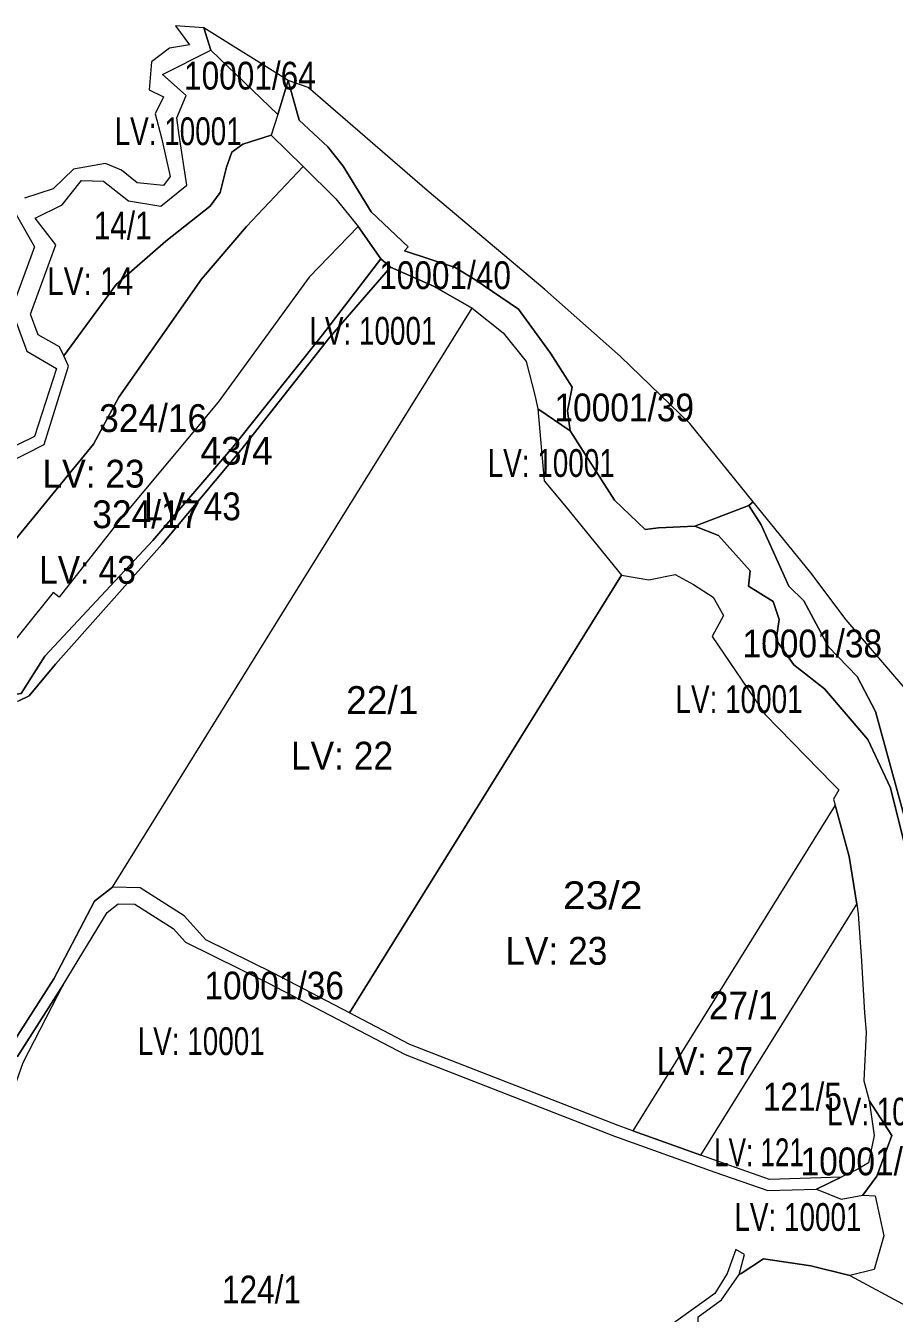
# Model space of a CAD drawing. Extents: x -713758 to -711119, y -1123067 to -1120789.
# Drawn here: x -711860.1 to -711547.6, y -1121251.9 to -1120788.6 of the extents above; entities that cross this region are included whole.
import ezdxf
from ezdxf.enums import TextEntityAlignment as Align

# ---------------------------------------------------------------- set-up
doc = ezdxf.new("R2010")
doc.units = 0
doc.header["$LTSCALE"] = 4
doc.layers.add('10', color=7, linetype='Continuous', lineweight=13)
doc.layers.add('11', color=7, linetype='Continuous')
doc.layers.add('13', color=7, linetype='Continuous')

msp = doc.modelspace()

# ---------------------------------------------------------------- linework, layer by layer
at = {"layer": '10'}
for points in [[(-711873, -1120949.11), (-711853.48, -1120939.28), (-711844.78, -1120911.14), (-711846.49, -1120907.42), (-711847.98, -1120904.16), (-711855.72, -1120899.85), (-711858.44, -1120892.41), (-711849.31, -1120867.47), (-711856.7, -1120857.83), (-711847.04, -1120852.99), (-711840.1, -1120844.3), (-711832.13, -1120844.47), (-711823.14, -1120851.63), (-711811.49, -1120853.48), (-711802.15, -1120845.94), (-711804.89, -1120828.03), (-711805.78, -1120821.79), (-711802.37, -1120813.65), (-711810.89, -1120806.19), (-711793.58, -1120797.41), (-711796.1, -1120789.32), (-711806.31, -1120788.6), (-711801.23, -1120795.5), (-711808.37, -1120796.72), (-711814.88, -1120801.58), (-711815.78, -1120811.62), (-711810.64, -1120814.14), (-711813.53, -1120820.28), (-711811.32, -1120828.91), (-711808.18, -1120842.85), (-711810.62, -1120846.06), (-711820.02, -1120845.09), (-711825.74, -1120840.53), (-711831.43, -1120838.21), (-711842.93, -1120840.16), (-711850.26, -1120847.24), (-711860.65, -1120850.69)], [(-711873, -1120949.11), (-711853.48, -1120939.28), (-711844.78, -1120911.14), (-711846.49, -1120907.42), (-711827.67, -1120881.76), (-711809.76, -1120866.12), (-711793.77, -1120853.57), (-711790.21, -1120848.55), (-711787.97, -1120839.48), (-711786.01, -1120834.13), (-711782.04, -1120831.21), (-711771.82, -1120827.96), (-711760.37, -1120839.22), (-711780.77, -1120860.87), (-711796.86, -1120879.81), (-711826.66, -1120922.21), (-711835.79, -1120939.19), (-711866.09, -1120976.19)], [(-711863.61, -1120856.54), (-711856.96, -1120868.18), (-711865.28, -1120890.65), (-711859.73, -1120905.68), (-711849.06, -1120911.92), (-711856.98, -1120936.42), (-711874.04, -1120944.64)], [(-711864.86, -1121154.76), (-711850.05, -1121131.56), (-711835.42, -1121103.63), (-711828.96, -1121098.5), (-711764.23, -1120994.34), (-711699.49, -1120890.18), (-711713.49, -1120882.3), (-711728.88, -1120875.51), (-711750.75, -1120900.66), (-711782.8, -1120941.31), (-711811.01, -1120975.09), (-711849.42, -1121018.37), (-711858.94, -1121029.71), (-711862.6, -1121031.5)], [(-711543.7, -1121084.05), (-711549.04, -1121062.79), (-711557.14, -1121045.46), (-711572.73, -1121027.16), (-711583.73, -1121018.59), (-711590.08, -1121009.55), (-711589, -1121002.29), (-711591.24, -1120995.77), (-711600.05, -1120990.23), (-711599.45, -1120984.79), (-711610.83, -1120972.06), (-711619.36, -1120968.62), (-711632.51, -1120969.32), (-711637.27, -1120969.86), (-711648.28, -1120959.29), (-711664.3, -1120934.34), (-711675.83, -1120926.4), (-711673.58, -1120952.37), (-711665.74, -1120961.8), (-711645.84, -1120986.3), (-711635.9, -1120988.02), (-711626.42, -1120986.06), (-711619.91, -1120989.63), (-711612.85, -1120994.25), (-711609.08, -1121000.83), (-711613.18, -1121008.42), (-711594.12, -1121036.42), (-711569.76, -1121061.38), (-711567.63, -1121063.57), (-711569.55, -1121066.91), (-711568.95, -1121069.06), (-711563.81, -1121087.54), (-711561.12, -1121104.7), (-711560.57, -1121108.21), (-711559.37, -1121125.17), (-711558.38, -1121143.78), (-711557.78, -1121150.75), (-711558.57, -1121168.22), (-711556.67, -1121175.27), (-711548.55, -1121187.95), (-711553.86, -1121202.53), (-711558.97, -1121209.34), (-711554.51, -1121209.67), (-711551.37, -1121224.06), (-711554.88, -1121236.09), (-711563.68, -1121238.26), (-711544.69, -1121248.43)], [(-711543.02, -1121027.95), (-711564.93, -1121002.34), (-711577.63, -1120985.46), (-711598.39, -1120959.85), (-711599.93, -1120961.23), (-711595.49, -1120968.21), (-711585.58, -1120990.25), (-711580.21, -1120995.57), (-711571.36, -1121012.06), (-711561.01, -1121022.81), (-711554.41, -1121035.4), (-711541.18, -1121083.42)], [(-711863.15, -1121159.5), (-711846.63, -1121133.64), (-711830.85, -1121107.66), (-711826.94, -1121104.56), (-711820.84, -1121104.73), (-711807.06, -1121113.47), (-711802.65, -1121118.36), (-711772.8, -1121133.08), (-711723.58, -1121158.82), (-711648.34, -1121188.11), (-711612.2, -1121201.06), (-711593.17, -1121207.73), (-711575.59, -1121207.21), (-711566.78, -1121202.95), (-711592.55, -1121203.71), (-711610.84, -1121197.3), (-711617.24, -1121195), (-711641.76, -1121186.22), (-711646.94, -1121184.36), (-711721.92, -1121155.17), (-711743.7, -1121143.79), (-711770.98, -1121129.52), (-711795.34, -1121117.5), (-711803.15, -1121108.84), (-711819.02, -1121098.78), (-711828.96, -1121098.5), (-711835.42, -1121103.63), (-711850.05, -1121131.56), (-711864.86, -1121154.76)], [(-711861.13, -1121161.65), (-711846.63, -1121133.64), (-711830.85, -1121107.66), (-711826.94, -1121104.56), (-711820.84, -1121104.73), (-711807.06, -1121113.47), (-711802.65, -1121118.36), (-711772.8, -1121133.08), (-711723.58, -1121158.82), (-711648.34, -1121188.11), (-711612.2, -1121201.06), (-711593.17, -1121207.73), (-711575.59, -1121207.21), (-711566.72, -1121210.82), (-711558.97, -1121209.34), (-711554.51, -1121209.67), (-711551.37, -1121224.06), (-711554.88, -1121236.09), (-711563.68, -1121238.26), (-711577.63, -1121234.79), (-711594.67, -1121232.25), (-711602.78, -1121237.53), (-711603.45, -1121237.97), (-711601.48, -1121230.75), (-711604.6, -1121228.99), (-711607.75, -1121237.57), (-711612.21, -1121244.74), (-711640.77, -1121265.29)], [(-711618.17, -1121253.17), (-711609.76, -1121247.05), (-711603.45, -1121237.97), (-711601.48, -1121230.75), (-711604.6, -1121228.99), (-711607.75, -1121237.57), (-711612.21, -1121244.74), (-711640.77, -1121265.29)]]:
    msp.add_lwpolyline(points, dxfattribs=at)
for points in [[(-711796.1, -1120789.32), (-711793.58, -1120797.41), (-711769.5, -1120820.49), (-711765.7, -1120808.3)], [(-711858.44, -1120892.41), (-711849.31, -1120867.47), (-711856.7, -1120857.83), (-711847.04, -1120852.99), (-711840.1, -1120844.3), (-711832.13, -1120844.47), (-711823.14, -1120851.63), (-711811.49, -1120853.48), (-711802.15, -1120845.94), (-711804.89, -1120828.03), (-711805.78, -1120821.79), (-711802.37, -1120813.65), (-711810.89, -1120806.19), (-711793.58, -1120797.41), (-711769.5, -1120820.49), (-711771.82, -1120827.96), (-711782.04, -1120831.21), (-711786.01, -1120834.13), (-711787.97, -1120839.48), (-711790.21, -1120848.55), (-711793.77, -1120853.57), (-711809.76, -1120866.12), (-711827.67, -1120881.76), (-711846.49, -1120907.42), (-711847.98, -1120904.16), (-711855.72, -1120899.85)], [(-711771.82, -1120827.96), (-711760.37, -1120839.22), (-711748.58, -1120850.82), (-711740.55, -1120860.88), (-711732.4, -1120872.48), (-711728.88, -1120875.51), (-711713.49, -1120882.3), (-711699.49, -1120890.18), (-711688.35, -1120899.1), (-711680.11, -1120909.39), (-711676.93, -1120921.47), (-711675.83, -1120926.4), (-711664.3, -1120934.34), (-711665.19, -1120927.13), (-711663.55, -1120918.61), (-711671.39, -1120906.45), (-711682.89, -1120890.63), (-711698.52, -1120879.86), (-711705.69, -1120875.55), (-711723.86, -1120869.63), (-711722.56, -1120868.11), (-711735.86, -1120855.55), (-711745.88, -1120839.18), (-711751.41, -1120832.11), (-711761.78, -1120822.6), (-711765.7, -1120808.3), (-711769.5, -1120820.49)], [(-711765.7, -1120808.3), (-711761.78, -1120822.6), (-711751.41, -1120832.11), (-711745.88, -1120839.18), (-711735.86, -1120855.55), (-711722.56, -1120868.11), (-711723.86, -1120869.63), (-711705.69, -1120875.55), (-711698.52, -1120879.86), (-711682.89, -1120890.63), (-711671.39, -1120906.45), (-711663.55, -1120918.61), (-711665.19, -1120927.13), (-711664.3, -1120934.34), (-711648.28, -1120959.29), (-711637.27, -1120969.86), (-711632.51, -1120969.32), (-711619.36, -1120968.62), (-711599.93, -1120961.23), (-711598.39, -1120959.85), (-711621.22, -1120931.7), (-711646.09, -1120907.6), (-711673.34, -1120883.49), (-711715.65, -1120847.94), (-711758.5, -1120810.84)], [(-711903.02, -1121028.08), (-711866.09, -1120976.19), (-711835.79, -1120939.19), (-711826.66, -1120922.21), (-711796.86, -1120879.81), (-711780.77, -1120860.87), (-711760.37, -1120839.22), (-711748.58, -1120850.82), (-711740.55, -1120860.88), (-711758.21, -1120879.11), (-711790.95, -1120924.02), (-711826.17, -1120966.22), (-711848.11, -1120994.25), (-711850.28, -1120992.52), (-711881.98, -1121031.84), (-711890.58, -1121032), (-711899.56, -1121029.17)], [(-711881.98, -1121031.84), (-711861.77, -1121028.84), (-711853.32, -1121015.43), (-711814.47, -1120973.83), (-711785.59, -1120940.28), (-711753.34, -1120899.79), (-711732.4, -1120872.48), (-711740.55, -1120860.88), (-711758.21, -1120879.11), (-711790.95, -1120924.02), (-711826.17, -1120966.22), (-711848.11, -1120994.25), (-711850.28, -1120992.52)], [(-711881.98, -1121031.84), (-711862.6, -1121031.5), (-711858.94, -1121029.71), (-711849.42, -1121018.37), (-711811.01, -1120975.09), (-711782.8, -1120941.31), (-711750.75, -1120900.66), (-711728.88, -1120875.51), (-711732.4, -1120872.48), (-711753.34, -1120899.79), (-711785.59, -1120940.28), (-711814.47, -1120973.83), (-711853.32, -1121015.43), (-711861.77, -1121028.84)], [(-711828.96, -1121098.5), (-711764.23, -1120994.34), (-711699.49, -1120890.18), (-711688.35, -1120899.1), (-711680.11, -1120909.39), (-711676.93, -1120921.47), (-711675.83, -1120926.4), (-711673.58, -1120952.37), (-711665.74, -1120961.8), (-711645.84, -1120986.3), (-711743.7, -1121143.79), (-711770.98, -1121129.52), (-711795.34, -1121117.5), (-711803.15, -1121108.84), (-711819.02, -1121098.78)], [(-711619.36, -1120968.62), (-711610.83, -1120972.06), (-711599.45, -1120984.79), (-711600.05, -1120990.23), (-711591.24, -1120995.77), (-711589, -1121002.29), (-711590.08, -1121009.55), (-711583.73, -1121018.59), (-711572.73, -1121027.16), (-711557.14, -1121045.46), (-711549.04, -1121062.79), (-711543.7, -1121084.05), (-711541.18, -1121083.42), (-711554.41, -1121035.4), (-711561.01, -1121022.81), (-711571.36, -1121012.06), (-711580.21, -1120995.57), (-711585.58, -1120990.25), (-711595.49, -1120968.21), (-711599.93, -1120961.23)], [(-711743.7, -1121143.79), (-711645.84, -1120986.3), (-711635.9, -1120988.02), (-711626.42, -1120986.06), (-711619.91, -1120989.63), (-711612.85, -1120994.25), (-711609.08, -1121000.83), (-711613.18, -1121008.42), (-711594.12, -1121036.42), (-711569.76, -1121061.38), (-711567.63, -1121063.57), (-711569.55, -1121066.91), (-711568.95, -1121069.06), (-711641.76, -1121186.22), (-711646.94, -1121184.36), (-711721.92, -1121155.17)], [(-711641.76, -1121186.22), (-711617.24, -1121195), (-711561.12, -1121104.7), (-711563.81, -1121087.54), (-711568.95, -1121069.06)], [(-711617.24, -1121195), (-711561.12, -1121104.7), (-711560.57, -1121108.21), (-711559.37, -1121125.17), (-711558.38, -1121143.78), (-711557.78, -1121150.75), (-711558.57, -1121168.22), (-711556.67, -1121175.27), (-711554.92, -1121187.89), (-711556.96, -1121197.7), (-711560.71, -1121200.01), (-711566.78, -1121202.95), (-711592.55, -1121203.71), (-711610.84, -1121197.3)], [(-711920.83, -1121168.71), (-711917.05, -1121183.35), (-711902.13, -1121180.77), (-711877.35, -1121179.44), (-711867.27, -1121179.34), (-711861.13, -1121161.65), (-711846.63, -1121133.64), (-711863.15, -1121159.5), (-711871.99, -1121162.53)], [(-711575.59, -1121207.21), (-711566.72, -1121210.82), (-711558.97, -1121209.34), (-711553.86, -1121202.53), (-711548.55, -1121187.95), (-711556.67, -1121175.27), (-711554.92, -1121187.89), (-711556.96, -1121197.7), (-711560.71, -1121200.01), (-711566.78, -1121202.95)], [(-711618.17, -1121253.17), (-711609.76, -1121247.05), (-711603.45, -1121237.97), (-711602.78, -1121237.53), (-711594.67, -1121232.25), (-711577.63, -1121234.79), (-711563.68, -1121238.26), (-711544.69, -1121248.43), (-711525.27, -1121257.57), (-711523.81, -1121258.22), (-711523.01, -1121446.38), (-711554.24, -1121447.4), (-711614.82, -1121453.59), (-711617.32, -1121453.99), (-711617.74, -1121353.58)]]:
    msp.add_lwpolyline(points, close=True, dxfattribs=at)

# ---------------------------------------------------------------- texts
at = {"layer": '11'}
for s, width, p in [('10001/64', 0.85, (-711779.481, -1120811.56)), ('14/1', 0.8, (-711825.26, -1120865.5)), ('10001/40', 0.85, (-711709.27, -1120883.36)), ('10001/39', 0.9, (-711644.8, -1120930.94)), ('324/16', 0.95, (-711814.3, -1120934.78)), ('324/17', 0.95, (-711816.77, -1120969.38)), ('10001/38', 0.9, (-711577.12, -1121015.88)), ('23/2', 1.1, (-711652.569, -1121106.46)), ('10001/36', 0.9, (-711770.75, -1121138.96)), ('27/1', 0.95, (-711601.99, -1121146.1)), ('121/5', 0.85, (-711580.71, -1121178.95)), ('10001/37', 0.9, (-711556.24, -1121202.23)), ('124/1', 0.85, (-711775.321, -1121248.33))]:
    msp.add_text(s, height=10, dxfattribs=dict(at, width=width)).set_placement(p, align=Align.CENTER)
for s, p in [('43/4', (-711784.31, -1120946.53)), ('22/1', (-711731.87, -1121036.23))]:
    msp.add_text(s, height=10, dxfattribs=at).set_placement(p, align=Align.CENTER)
at = {"layer": '13'}
for s, width, p in [('LV: 10001 ', 0.75, (-711803.906, -1120831.56)), ('LV: 14 ', 0.8, (-711835.498, -1120885.5)), ('LV: 10001 ', 0.75, (-711733.83, -1120903.36)), ('LV: 10001 ', 0.75, (-711669.661, -1120950.94)), ('LV: 23 ', 0.95, (-711833.975, -1120954.78)), ('LV: 43 ', 0.9, (-711798.464, -1120966.53)), ('LV: 43 ', 0.9, (-711836.244, -1120989.38)), ('LV: 10001 ', 0.75, (-711602.082, -1121035.88)), ('LV: 22 ', 0.95, (-711744.586, -1121056.23)), ('LV: 23 ', 0.95, (-711667.459, -1121126.46)), ('LV: 10001 ', 0.75, (-711795.611, -1121158.96)), ('LV: 27 ', 0.9, (-711614.135, -1121166.1)), ('LV: 10001 ', 0.75, (-711547.508, -1121184.28)), ('LV: 121 ', 0.7, (-711594.998, -1121198.95)), ('LV: 10001 ', 0.75, (-711580.9, -1121222.23))]:
    msp.add_text(s, height=10, dxfattribs=dict(at, width=width)).set_placement(p, align=Align.CENTER)

doc.saveas('drawing.dxf')
